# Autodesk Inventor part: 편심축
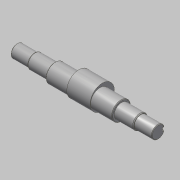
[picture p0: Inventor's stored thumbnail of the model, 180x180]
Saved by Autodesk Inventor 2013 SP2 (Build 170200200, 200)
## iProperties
Created: 2015-10
Part Number: 편심축
Document SubType Name: Modeling
Designer: mdu
Density: 7.86 g/cm^3
Material: 강철, 연강
Mass: 1327.14 g
Surface Area: 247.481 cm^2
Volume: 168.848 cm^3
Author: mdu
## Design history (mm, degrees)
sketch "스케치1"
  geometry: L1 (-20.5, -41.331)-(-20.5, 32.669) reference; L2 (7.5, -30.031)-(7.5, 21.369) reference; L3 (135.5, -30.331)-(135.5, 21.669) reference; L4 (121.5, 21.369)-(121.5, -30.031) reference; L5 (184.5, -4.331)-(-57.5, -4.331); L6 (184.5, -4.331)-(184.5, 6.669); L7 (154.5, 8.169)-(121.5, 8.169); L8 (121.5, 8.169)-(121.5, 11.669); L9 (121.5, 11.669)-(7.5, 11.669); L10 (7.5, 11.669)-(7.5, 8.169); L11 (7.5, 8.169)-(-27.5, 8.169); L12 (-27.5, 8.169)-(-27.5, 6.669); L13 (-27.5, 6.669)-(-57.5, 6.669); L14 (-57.5, 6.669)-(-57.5, -4.331); L15 (154.5, 8.169)-(154.5, 6.669); L16 (154.5, 6.669)-(184.5, 6.669); C1 r 32.5 at (64.5, -4.331) reference; 1 further point
  constraints: 24 end point, 8 perpendicular, 5 point on line, 3 parallel, 2 collinear
  dimensions: "d1" = 25 diameter of L11 L5; "d2" = 32 diameter of L9 L5; "d3" = 22 diameter of L13 L5; "d4" = 35 distance of L10.end L11.end; "d5" = 30 distance of L12.end L13.end; "d15" = 33 distance of L7.start L7.end; "d26" = 30 distance of L15.end L6.end
revolve "회전1" sketch "스케치1" stored, may be unused: angle "d6" = 90 deg
node "작업 평면1"
sketch "스케치2"
  geometry: C1 r 16 at (0, 0) reference; C2 r 16 at (0, 0) reference; C3 r 20.75 at (0, 4); C4 r 16 at (0, 0) reference; 1 further point
  constraints: 1 centre point, 1 vertical alignment
  dimensions: "d8" = 41.5 diameter of C3; "d25" = 4 distance of C3.centre C1.centre
extrude "돌출1" join sketch "스케치2" stored distance "d9" = 40; taper "d10" = 0 deg
chamfer "모따기1" distance "d11" = 1; stored, may be unused: second distance "d12" = 2, angle "d13" = 45 deg
node "작업 평면2"
sketch "스케치3"
  geometry: L1 (-15, -10)-(-15, 10) reference; L2 (-15, 3)-(0, 3); L3 (0, -3)-(-15, -3); A1 r 3 centre (0, 0) between (0, -3) and (0, 3); 2 further points
  constraints: 4 end point, 2 perpendicular, 2 point on circle, 2 point on line, 2 tangent, 1 centre point, 1 horizontal alignment, 1 midpoint
  dimensions: "d16" = 18 dimension on A1 L1; "d17" = 6 distance between parallel lines of L3 L2
extrude "돌출2" cut sketch "스케치3" distance "d18" = 3.5; taper "d19" = 0 deg
node "작업 평면3"
chamfer "모따기2" distance "d27" = 1.5; stored, may be unused: second distance "d28" = 2, angle "d29" = 30 deg
chamfer "모따기3" distance "d30" = 1.5; stored, may be unused: second distance "d31" = 2, angle "d32" = 30 deg
node "솔리드1"
mirror "대칭1"
node "참조1"
node "참조2"
node "참조3"
node "참조4"
node "참조5"
node "투영된 루프1"
